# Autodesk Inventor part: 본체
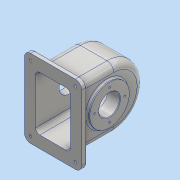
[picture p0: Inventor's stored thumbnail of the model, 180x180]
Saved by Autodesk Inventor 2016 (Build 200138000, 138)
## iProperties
Created: 2018-11
Part Number: 본체
Material: 알루미늄 6061
Document SubType Name: Modeling
Designer: user
Density: 2.7 g/cm^3
Appearance: 알루미늄 - 평지
Mass: 1092.25 g
Surface Area: 1179.16 cm^2
Volume: 404.538 cm^3
Author: user
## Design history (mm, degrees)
sketch "스케치1"
  geometry: L1 (-55, -75)-(55, -75); L2 (55, -75)-(55, 75); L3 (55, 75)-(-55, 75); L4 (-55, 75)-(-55, -75); L5 (-55, -75)-(55, 75); L6 (55, -75)-(-55, 75); 1 further point
  constraints: 12 end point, 2 midpoint, 2 parallel, 1 horizontal, 1 perpendicular
  dimensions: "d0" = 110 distance of L2.end L3.end; "d1" = 150 distance of L1.end L2.end
extrude "돌출1" new body sketch "스케치1" distance "d2" = 10; taper "d3" = 0 deg
sketch "스케치2"
  geometry: L1 (0, 75)-(0, -75) reference; L2 (78, -58)-(10, -58); L3 (78, 58)-(10, 58); L4 (10, 75)-(10, -75) reference; L5 (10, -58)-(10, 58); L6 (10, -75)-(10, 75) reference; L7 (0, -75)-(0, 75) reference; A1 r 58 centre (78, 0) between (78, -58) and (78, 58); 4 further points
  constraints: 6 end point, 3 midpoint, 3 vertical alignment, 2 horizontal, 2 point on circle, 2 point on line, 1 centre point, 1 collinear, 1 horizontal alignment
  dimensions: "d4" = 116 diameter of A1; "d5" = 78 distance from line of L1 A1.centre; "d8" = 116 distance between parallel lines of L3 L2
extrude "돌출2" join sketch "스케치2" stored distance "d6" = 77; taper "d7" = 0 deg
feature "쉘1" dims "d9" = 6, "d10" = 10, "d11" = 5
sketch "스케치3"
  geometry: L1 (-75, 0)-(75, 0) reference; C1 r 38 at (0, 65); 2 further points
  constraints: 1 centre point, 1 midpoint, 1 vertical alignment
  dimensions: "d12" = 76 diameter of C1; "d13" = 65 distance from line of L1 C1.centre
extrude "돌출3" join sketch "스케치3" distance "d14" = 10; taper "d15" = 0 deg
sketch "스케치4"
  geometry: L1 (-75, 0)-(75, 0) reference; C1 r 38 at (0, 65); 2 further points
  constraints: 1 centre point, 1 midpoint, 1 vertical alignment
  dimensions: "d16" = 76 diameter of C1; "d17" = 65 distance from line of L1 C1.centre
extrude "돌출4" join sketch "스케치4" distance "d18" = 5; taper "d19" = 0 deg
sketch "스케치5"
  geometry: L1 (19.5, 93)-(19.5, 65); L2 (43.5, 27)-(43.5, 103) reference; L3 (19.5, 93)-(33.5, 104.747); L4 (33.5, 78)-(33.5, 130) reference; L5 (19.5, 65)-(33.5, 65); L6 (33.5, 65)-(33.5, 104.747); 2 further points
  constraints: 8 end point, 1 collinear, 1 horizontal, 1 horizontal alignment, 1 midpoint, 1 point on line, 1 vertical
  dimensions: "d20" = 28 distance of L1.start L1.end; "d21" = 50 deg angle of L1 L3; "d23" = 24 distance between parallel lines of L1 L2
revolve "회전1" sketch "스케치5" stored, may be unused: angle "d24" = 90 deg
sketch "스케치6"
  geometry: C1 r 38 at (0, 0) reference; C2 r 20 at (0, 0); 1 further point
  constraints: 1 centre point, 1 coincident
  dimensions: "d25" = 40 diameter of C2
extrude "돌출5" cut sketch "스케치6" stored distance "d26" = 5; taper "d27" = 0 deg
sketch "스케치7"
  geometry: L1 (-75, -65)-(75, -65) reference; C1 r 29 at (0, 0); C2 r 38 at (0, 0) reference; 3 further points
  constraints: 1 centre point, 1 concentric, 1 midpoint, 1 vertical alignment
  dimensions: "d28" = 58 diameter of C1; "d29" = 29 distance of point (0, 29) C1.centre
hole "구멍1" sketch "스케치7" at (0, 29) diameter "d30" = 3.242; stored, may be unused: countersink angle "d34" = 90 deg, drill point angle "d36" = 118 deg; dims "d31" = 8, "d32" = 4, "d33" = 2, "d35" = 10
node "작업 평면1"
sketch "스케치8"
  geometry: C1 r 6 at (0, 0); 1 further point
  constraints: 1 centre point, 1 coincident
  dimensions: "d41" = 12 diameter of C1
extrude "돌출6" join sketch "스케치8" stored distance "d42" = 5; taper "d43" = 5 deg
sketch "스케치9"
  geometry: 1 further point
hole "구멍2" sketch "스케치9" at (0, 0) diameter "d44" = 4.459; stored, may be unused: countersink angle "d48" = 90 deg, drill point angle "d50" = 118 deg; dims "d45" = 10, "d46" = 4, "d47" = 2, "d49" = 12.8
fillet "모깎기1" dims "d51" = 12
sketch "스케치10"
  geometry: C1 r 6 at (43, 63); A1 r 12 centre (43, 63) between (55, 63) and (43, 75) reference; 1 further point
  constraints: 1 centre point, 1 coincident
  dimensions: "d52" = 12 diameter of C1
extrude "돌출7" cut sketch "스케치10" distance "d53" = 4; taper "d54" = 0 deg
sketch "스케치11"
  geometry: C1 r 2.5 at (0, 0); C2 r 6 at (0, 0) reference; 1 further point
  constraints: 1 centre point, 1 concentric
  dimensions: "d55" = 5 diameter of C1
extrude "돌출8" cut sketch "스케치11" stored distance "d56" = 4; taper "d57" = 0 deg
fillet "모깎기2" dims "d64" = 13
fillet "모깎기3" dims "d65" = 8
fillet "모깎기4" dims "d66" = 3
fillet "모깎기5" dims "d67" = 3
chamfer "모따기1" distance "d68" = 1; stored, may be unused: second distance "d69" = 2, angle "d70" = 45 deg
sketch "스케치12"
  geometry: L1 (-17.5, -78)-(68.5, -78) reference; L2 (-13, 0)-(-13, -65) reference; 2 further points
  constraints: 1 other
  dimensions: "d71" = 40 distance from line of L1 point (25.5, -38); "d72" = 38.5 distance from line of L2 point (25.5, -38)
feature "엠보싱1" sketch "스케치12" dims "d0" = 110, "d1" = 150, "d4" = 116, "d5" = 78, "d8" = 116, "d73" = 0.5, "d74" = 0
sketch "스케치13" dims "d75" = 58
  geometry: C1 r 38 at (0, 0) reference; 3 further points
  constraints: 2 vertical alignment, 3 other
hole "구멍3" sketch "스케치13" at (0, 29) diameter "d76" = 3.242; stored, may be unused: countersink angle "d80" = 90 deg, drill point angle "d82" = 118 deg; dims "d77" = 8, "d78" = 4, "d79" = 2, "d81" = 10
node "솔리드1"
pattern_circular "원형 패턴1" dims angle "d38" = 360 deg
pattern_linear "직사각형 패턴1" dims "d60" = 86, "d63" = 126
pattern_circular "원형 패턴2" dims angle "d84" = 360 deg
other parameters: "d40" = 142
